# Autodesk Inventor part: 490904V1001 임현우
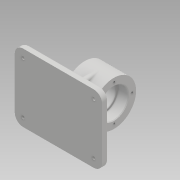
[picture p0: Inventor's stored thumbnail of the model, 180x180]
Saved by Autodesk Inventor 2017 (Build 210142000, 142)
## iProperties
Part Number: 490904V1001 임현우
Material: 일반
Document SubType Name: Modeling
Designer: 603-17
Density: 1 g/cm^3
Appearance: 기본값
Author: 603-17
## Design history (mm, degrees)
sketch "스케치1"
  geometry: L1 (63, 49)-(-63, 49); L2 (-63, 49)-(-63, -49); L3 (-63, -49)-(63, -49); L4 (63, -49)-(63, 49); L5 (63, 49)-(-63, -49); L6 (-63, 49)-(63, -49); 1 further point
  constraints: 12 end point, 2 midpoint, 2 parallel, 1 horizontal, 1 perpendicular
  dimensions: "d0" = 126 distance of L2.end L3.end; "d1" = 98 distance of L1.end L2.end
extrude "돌출1" new body sketch "스케치1" distance "d2" = 9; taper "d3" = 0 deg
node "작업 평면1"
sketch "스케치2"
  geometry: L1 (0, 49)-(9, 49) reference; L2 (9, 49)-(9, -49) reference; L3 (9, -49)-(0, -49) reference; L4 (0, -49)-(0, 49) reference; L5 (0, 49)-(0, -13); L6 (0, -13)-(59, -13); C1 r 32 at (59, -13); 1 further point
  constraints: 4 end point, 1 centre point, 1 coincident, 1 horizontal, 1 vertical
  dimensions: "d5" = 62 distance of L1.start L5.end; "d6" = 59 distance of L5.end L6.end; "d7" = 64 diameter of C1
extrude "돌출2" join sketch "스케치2" stored distance "d8" = 42; taper "d9" = 0 deg
sketch "스케치3"
  geometry: L1 (0, 49)-(9, 49) reference; L2 (9, 49)-(9, -49) reference; L3 (9, -49)-(0, -49) reference; L4 (0, -49)-(0, 49) reference; L5 (59, -45)-(4.5, -45); L6 (59, 19)-(4.5, 19); L7 (4.5, -45)-(4.5, 19); A1 r 32 centre (59, -13) between (59, -45) and (59, 19) reference; 1 further point
  constraints: 6 end point, 2 point on circle, 1 horizontal, 1 parallel, 1 perpendicular, 1 tangent
extrude "돌출3" join sketch "스케치3" stored distance "d10" = 8; taper "d11" = 0 deg
node "작업 평면2"
sketch "스케치4"
  geometry: L1 (126, 9)-(126, 0) reference; L2 (126, 0)-(0, 0) reference; L3 (0, 0)-(0, 9) reference; L4 (0, 9)-(59, 9) reference; L5 (59, 9)-(59, 27) reference; L6 (59, 27)-(42, 27) reference; L7 (42, 27)-(42, 91) reference; L8 (42, 91)-(84, 91) reference; L9 (84, 91)-(84, 27) reference; L10 (84, 27)-(67, 27) reference; L11 (67, 27)-(67, 9) reference; L12 (67, 9)-(126, 9) reference; L13 (46, 0)-(80, 0); L14 (80, 0)-(80, 42.607); L15 (80, 42.607)-(46, 42.607); L16 (46, 42.607)-(46, 0); 3 further points
  constraints: 8 end point, 2 coincident, 2 midpoint, 2 parallel, 1 horizontal, 1 perpendicular
  dimensions: "d13" = 34 distance of L14.end L15.end
extrude "돌출4" join sketch "스케치4" stored distance "d14" = 8; taper "d15" = 0 deg
fillet "모깎기1" dims "d16" = 12
fillet "모깎기2" dims "d17" = 3
fillet "모깎기3" dims "d18" = 3
fillet "모깎기4" dims "d19" = 3
fillet "모깎기5" dims "d20" = 3
fillet "모깎기6" dims "d21" = 3
sketch "스케치5"
  geometry: L1 (-59, -50)-(33, -50) reference; L2 (36, -53)-(36, -59) reference; L3 (36, -59)-(-62, -59) reference; L4 (-62, -59)-(-62, -53) reference; C1 r 32 at (0, 0) reference; C2 r 18 at (0, 0); A1 r 3 centre (-59, -53) between (-59, -50) and (-62, -53) reference; A2 r 3 centre (33, -53) between (36, -53) and (33, -50) reference; 1 further point
  constraints: 1 centre point, 1 coincident
  dimensions: "d22" = 36 diameter of C2
extrude "돌출5" cut sketch "스케치5" stored distance "d23" = 8; taper "d24" = 0 deg
sketch "스케치6"
  geometry: C1 r 21 at (0, 0); 1 further point
  constraints: 1 centre point
  dimensions: "d25" = 42 diameter of C1
extrude "돌출6" cut sketch "스케치6" distance "d26" = 15; taper "d27" = 0 deg
fillet "모깎기7" dims "d28" = 0.3
chamfer "모따기1" distance "d29" = 1; stored, may be unused: second distance "d30" = 2, angle "d31" = 45 deg
sketch "스케치7" dims "d32" = 52
  geometry: L1 (-59, -50)-(33, -50) reference; L2 (36, -53)-(36, -59) reference; L3 (36, -59)-(-62, -59) reference; L4 (-62, -59)-(-62, -53) reference; L5 (0, 0)-(0, 26); C1 r 22 at (0, 0) reference; C2 r 32 at (0, 0) reference; A1 r 3 centre (-59, -53) between (-59, -50) and (-62, -53) reference; A2 r 3 centre (33, -53) between (36, -53) and (33, -50) reference; 1 further point
  constraints: 2 end point, 1 coincident, 1 vertical, 1 vertical alignment, 2 other
hole "구멍1" sketch "스케치7" at (0, 26) diameter "d33" = 3.459; stored, may be unused: countersink angle "d37" = 90 deg, drill point angle "d39" = 118 deg; dims "d34" = 8, "d35" = 4, "d36" = 2, "d38" = 10
sketch "스케치8"
  geometry: L1 (60, -37)-(60, 37) reference; L2 (51, 46)-(5.472, 46) reference; L3 (-1, 46.607)-(1, 46.607) reference; L4 (-5.472, 46)-(-51, 46) reference; L5 (-60, 37)-(-60, -37) reference; L6 (-51, -46)-(51, -46) reference; L7 (7, 20)-(7, 42) reference; L8 (14, 20)-(7, 20) reference; L9 (20, 12)-(20, 14) reference; L10 (7, 6)-(14, 6) reference; L11 (7, -16)-(7, 6) reference; L12 (-1, -22)-(1, -22) reference; L13 (-7, 6)-(-7, -16) reference; L14 (-14, 6)-(-7, 6) reference; L15 (-20, 14)-(-20, 12) reference; L16 (-7, 20)-(-14, 20) reference; L17 (-7, 42)-(-7, 20) reference; C1 r 2.25 at (51, 37); C2 r 2.25 at (-51, 37); C3 r 2.25 at (-51, -37); C4 r 2.25 at (51, -37); A1 r 9 centre (51, -37) between (51, -46) and (60, -37) reference; A2 r 9 centre (51, 37) between (60, 37) and (51, 46) reference; A3 r 9 centre (-51, 37) between (-51, 46) and (-60, 37) reference; A4 r 9 centre (-51, -37) between (-60, -37) and (-51, -46) reference; A5 r 6 centre (1, 42) between (7, 42) and (5.472, 46) reference; A6 r 6 centre (14, 14) between (20, 14) and (14, 20) reference; A7 r 6 centre (14, 12) between (14, 6) and (20, 12) reference; A8 r 6 centre (1, -16) between (1, -22) and (7, -16) reference; A9 r 6 centre (-1, -16) between (-7, -16) and (-1, -22) reference; A10 r 6 centre (-14, 12) between (-20, 12) and (-14, 6) reference; A11 r 6 centre (-14, 14) between (-14, 20) and (-20, 14) reference; A12 r 6 centre (-1, 42) between (-5.472, 46) and (-7, 42) reference; 1 further point
  constraints: 4 centre point, 4 coincident, 2 other
  dimensions: "d43" = 4.5 diameter of C2; "d44" = 4.5 diameter of C1; "d45" = 4.5 diameter of C3; "d46" = 4.5 diameter of C4
extrude "돌출7" cut sketch "스케치8" stored distance "d47" = 15; taper "d48" = 0 deg
sketch "스케치9"
  geometry: L1 (60, -37)-(60, 37) reference; L2 (51, 46)-(5.472, 46) reference; L3 (-1, 46.607)-(1, 46.607) reference; L4 (-5.472, 46)-(-51, 46) reference; L5 (-60, 37)-(-60, -37) reference; L6 (-51, -46)-(51, -46) reference; L7 (7, 20)-(7, 42) reference; L8 (14, 20)-(7, 20) reference; L9 (20, 12)-(20, 14) reference; L10 (7, 6)-(14, 6) reference; L11 (7, -16)-(7, 6) reference; L12 (-1, -22)-(1, -22) reference; L13 (-7, 6)-(-7, -16) reference; L14 (-14, 6)-(-7, 6) reference; L15 (-20, 14)-(-20, 12) reference; L16 (-7, 20)-(-14, 20) reference; L17 (-7, 42)-(-7, 20) reference; C1 r 2.25 at (-51, -37) reference; C2 r 2.25 at (51, 37) reference; C3 r 2.25 at (-51, 37) reference; C4 r 2.25 at (51, -37) reference; C5 r 4 at (-51, 37); C6 r 4 at (51, 37); C7 r 4 at (51, -37); C8 r 4 at (-51, -37); A1 r 9 centre (51, -37) between (51, -46) and (60, -37) reference; A2 r 9 centre (51, 37) between (60, 37) and (51, 46) reference; A3 r 9 centre (-51, 37) between (-51, 46) and (-60, 37) reference; A4 r 9 centre (-51, -37) between (-60, -37) and (-51, -46) reference; A5 r 6 centre (1, 42) between (7, 42) and (5.472, 46) reference; A6 r 6 centre (14, 14) between (20, 14) and (14, 20) reference; A7 r 6 centre (14, 12) between (14, 6) and (20, 12) reference; A8 r 6 centre (1, -16) between (1, -22) and (7, -16) reference; A9 r 6 centre (-1, -16) between (-7, -16) and (-1, -22) reference; A10 r 6 centre (-14, 12) between (-20, 12) and (-14, 6) reference; A11 r 6 centre (-14, 14) between (-14, 20) and (-20, 14) reference; A12 r 6 centre (-1, 42) between (-5.472, 46) and (-7, 42) reference; 1 further point
  constraints: 4 centre point, 4 coincident, 2 other
  dimensions: "d49" = 8 diameter of C5; "d50" = 8 diameter of C6; "d51" = 8 diameter of C7; "d52" = 8 diameter of C8
extrude "돌출8" cut sketch "스케치9" distance "d53" = 4.4; taper "d54" = 0 deg
node "솔리드1"
mirror "미러1"
pattern_circular "원형 패턴1" dims angle "d41" = 360 deg
mirror "미러2"
node "절단 모서리 투영1"
node "절단 모서리 투영2"
node "절단 모서리 투영3"
node "절단 모서리 투영4"
node "절단 모서리 투영5"
node "절단 모서리 투영6"
node "절단 모서리 투영7"
other parameters: "d4" = 0, "d12" = -62
